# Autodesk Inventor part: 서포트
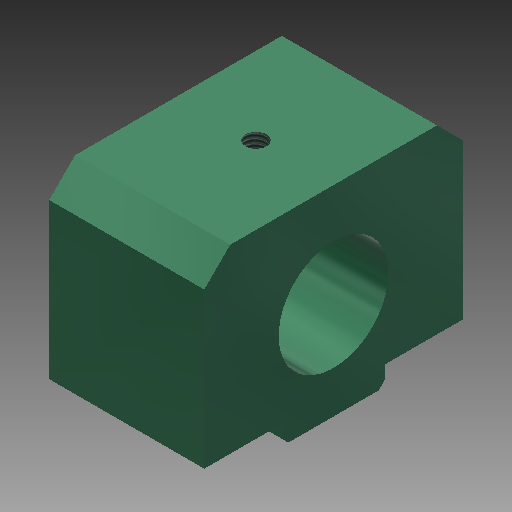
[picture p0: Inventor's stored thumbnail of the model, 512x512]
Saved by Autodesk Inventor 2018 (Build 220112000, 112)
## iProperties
Created: 2019-04
Part Number: 서포트
Material: 알루미늄 6061
Document SubType Name: Modeling
Designer: mduedu
Density: 1 g/cm^3
Appearance: 매끄러움 - 짙은 바다 녹색
Author: mduedu
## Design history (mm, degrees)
sketch "스케치1"
  geometry: L1 (3, 20)-(31, 20); L2 (31, 20)-(31, -20); L3 (31, -20)-(3, -20); L4 (0, -8)-(0, 8); L5 (0, 8)-(3, 8); L6 (3, 8)-(3, 20); L7 (0, 0)-(31, 0); L8 (0, -8)-(3, -8); L9 (3, -8)-(3, -20); 1 further point
  constraints: 18 end point, 3 symmetric about line, 2 horizontal, 2 midpoint, 2 parallel, 2 perpendicular, 1 coincident
  dimensions: "d3" = 31 distance between parallel lines of L4 L2; "d5" = 16 distance of L4.start L4.end; "d6" = 40 distance between parallel lines of L3 L1; "d7" = 3 distance between parallel lines of L4 L9
extrude "돌출1" new body sketch "스케치1" distance "d8" = 24; taper "d9" = 0 deg
chamfer "모따기1" distance "d10" = 4; stored, may be unused: second distance "d11" = 2, angle "d12" = 45 deg
chamfer "모따기2" distance "d13" = 1; stored, may be unused: second distance "d14" = 2, angle "d15" = 45 deg
sketch "스케치2"
  geometry: L1 (7, 0)-(-7, 0) reference; L2 (20, 3)-(8, 3) reference; 3 further points
  constraints: 1 midpoint, 1 vertical alignment
  dimensions: "d24" = 12 distance from line of point (0, 15) L2
hole "구멍1" sketch "스케치2" at (0, 15) diameter "d17" = 17; stored, may be unused: countersink angle "d21" = 90 deg, drill point angle "d23" = 118 deg; dims "d18" = 6, "d19" = 21, "d20" = 3, "d22" = 8
sketch "스케치3"
  geometry: L1 (0, 32)-(0, 0) reference; 3 further points
  constraints: 1 horizontal alignment, 1 midpoint
  dimensions: "d25" = 12 distance from line of point (12, 16) L1
hole "구멍2" sketch "스케치3" at (12, 16) diameter "d26" = 3.242; stored, may be unused: countersink angle "d30" = 90 deg, drill point angle "d32" = 118 deg; dims "d27" = 6, "d28" = 21, "d29" = 3, "d31" = 8
sketch "스케치4"
  geometry: L1 (0, -8)-(24, -8); L2 (24, 0.5)-(24, -16.5) reference; L3 (0, -28)-(0, -24) reference; 4 further points
  constraints: 2 end point, 2 symmetric about line, 1 horizontal, 1 horizontal alignment, 1 midpoint
  dimensions: "d33" = 6 distance from line of point (6, -22) L3; "d34" = 12 distance of point (18, -22) point (6, -22); "d35" = 28 distance of point (6, 6) point (6, -22); "d36" = 14 distance from line of point (6, -22) L1 (derived)
hole "구멍3" sketch "스케치4" at (6, -22), (18, -22), (18, 6), (6, 6) diameter "d37" = 3.242; stored, may be unused: countersink angle "d41" = 90 deg, drill point angle "d43" = 118 deg; dims "d38" = 9, "d39" = 21, "d40" = 3, "d42" = 11
node "솔리드1"
